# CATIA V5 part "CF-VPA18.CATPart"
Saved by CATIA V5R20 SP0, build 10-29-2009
Part number: CF-VPA18
Bounding box of the stored display mesh (mm): x 0 to 39.5, y -9 to 9, z -9 to 9
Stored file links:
  C:\Users\Utente\Desktop\IO LAVORO\3D X SITO CF\X SITO\PLASTICA\CF-VPA\CF-VPA18.CATPart
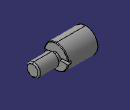
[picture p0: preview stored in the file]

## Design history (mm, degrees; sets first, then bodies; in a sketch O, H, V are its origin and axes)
Set1
  DatumSurface1 to DatumSurface30 "CF-VPA18"
Body1 (main body)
